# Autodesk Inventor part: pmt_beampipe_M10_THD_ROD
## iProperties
Shininess: 64.0
Length Units: 11269
Angle Units: 11279
Time Units: 11290
Mass Units: 11283
Length Display Precision: 3
Angle Display Precision: 2
Compacted: True
Part Number: pmt_beampipe_M10_THD_ROD
Document SubType Name: Modeling
Created: 2004-08
Designer: John Blackburn
Manufacturer: Standard
Standards Organization: Custom
Material: Stainless Steel, Austenitic
Density: 0.0
Volumn: 0.0
Area: 0.0
PropertySet Name: Model Information
Control State: 0
Master: False
Checked Out: False
Author: John Blackburn
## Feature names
1. Extrusion1
2. Chamfer1
